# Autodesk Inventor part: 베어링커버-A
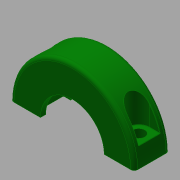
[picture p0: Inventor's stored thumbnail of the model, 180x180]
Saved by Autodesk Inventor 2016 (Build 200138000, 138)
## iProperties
Created: 2018-01
Part Number: 베어링커버-A
Material: 일반
Document SubType Name: Modeling
Designer: mduedu
Density: 1 g/cm^3
Appearance: 진녹색
Author: mduedu
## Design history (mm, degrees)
sketch "스케치1"
  geometry: L1 (-17.5, 0)-(17.5, 0); A1 r 17.5 centre (0, 0) between (-17.5, 0) and (17.5, 0); 2 further points
  constraints: 2 coincident, 2 end point, 2 point on circle, 1 centre point, 1 horizontal, 1 midpoint
  dimensions: "d0" = 35 diameter of A1
extrude "돌출1" new body sketch "스케치1" stored distance "d1" = 10; taper "d2" = 0 deg
sketch "스케치2"
  geometry: C1 r 11 at (0, 0); C2 r 9 at (0, 0); 1 further point
  constraints: 2 centre point, 2 coincident
  dimensions: "d3" = 22 diameter of C1; "d4" = 18 diameter of C2
extrude "돌출2" cut sketch "스케치2" stored distance "d5" = 7; taper "d6" = 0 deg
extrude "돌출3" cut sketch "스케치2" stored distance "d7" = 7; taper "d8" = 0 deg
fillet "모깎기1" dims "d9" = 0.3
fillet "모깎기2" dims "d10" = 1
node "작업 평면1"
sketch "스케치3"
  geometry: L1 (-15.5, -3.5)-(33.5, -3.5) reference; L2 (-4.771, -6.5)-(-7.771, -6.5); L3 (-7.771, -6.5)-(-7.771, -0.5); L4 (-7.771, -0.5)-(-4.771, -0.5); L5 (-0.46, -7)-(1.517, -7) reference; L6 (1.517, -7)-(1.517, -8.5) reference; L7 (1.517, -8.5)-(-6.724, -8.5) reference; L8 (-7.771, -7.5)-(-7.771, 0.5) reference; L9 (-6.724, 1.5)-(1.517, 1.5) reference; L10 (1.517, 1.5)-(1.517, 0) reference; L11 (1.517, 0)-(-0.46, 0) reference; L12 (-0.798, -0.3)-(-0.798, -6.7) reference; L13 (18.798, -6.7)-(18.798, -0.3) reference; L14 (18.46, 0)-(16.483, 0) reference; L15 (16.483, 0)-(16.483, 1.5) reference; L16 (16.483, 1.5)-(24.724, 1.5) reference; L17 (25.771, 0.5)-(25.771, -7.5) reference; L18 (24.724, -8.5)-(16.483, -8.5) reference; L19 (16.483, -8.5)-(16.483, -7) reference; L20 (16.483, -7)-(18.46, -7) reference; A1 r 3 centre (-4.771, -3.5) between (-4.771, -6.5) and (-4.771, -0.5); 1 further point
  constraints: 6 end point, 2 point on circle, 2 tangent, 1 centre point, 1 collinear, 1 horizontal, 1 parallel, 1 perpendicular, 1 point on line, 8 other
  dimensions: "d12" = 6 distance between parallel lines of L4 L2; "d14" = 6 dimension on A1 L3
extrude "돌출4" cut sketch "스케치3" stored distance "d15" = 0; taper "d16" = 0 deg
sketch "스케치4"
  geometry: 7 further points
  constraints: 4 vertical alignment, 2 horizontal alignment
sketch "스케치5"
  geometry: 2 further points
  constraints: 2 other
hole "구멍1" sketch "스케치5" at (-22.771, 3.5), (4.771, 3.5) diameter "d17" = 3.4; stored, may be unused: countersink angle "d21" = 90 deg, drill point angle "d23" = 0 deg; dims "d18" = 6, "d19" = 4, "d20" = 2, "d22" = 8
fillet "모깎기3" dims "d24" = 0.1
node "솔리드1"
mirror "대칭1"
node "절단 모서리 투영1"
other parameters: "d11" = -5
